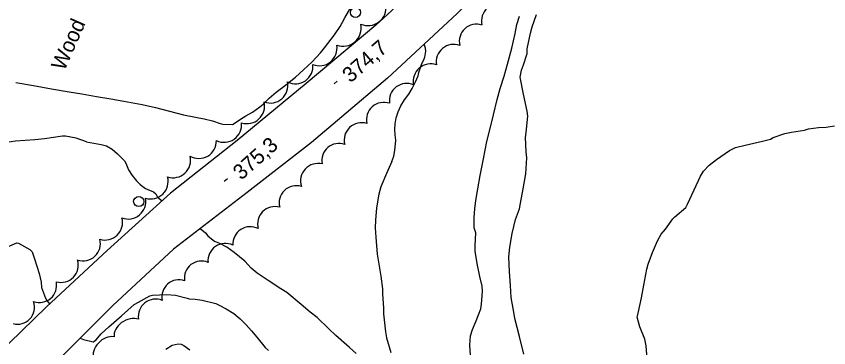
# Model space of a CAD drawing. Extents: x 287698 to 290158, y 5234163 to 5237182.
# Drawn here: x 287954.6 to 288115.1, y 5235215.8 to 5235281.3 of the extents above; entities that cross this region are included whole.
import ezdxf

# ---------------------------------------------------------------- set-up
doc = ezdxf.new("R2010")
doc.units = 0
for name, color, linetype in [('Niveau 1', 7, 'Continuous'), ('Niveau 2', 7, 'Continuous'), ('Niveau 21', 7, 'Continuous'), ('Niveau 3', 7, 'Continuous'), ('Niveau 36', 7, 'Continuous'), ('Niveau 44', 7, 'Continuous')]:
    doc.layers.add(name, color=color, linetype=linetype)

msp = doc.modelspace()

# ---------------------------------------------------------------- linework, layer by layer
at = {"layer": 'Niveau 1'}
for points in [[(288052.13, 5235235.69), (288052.56, 5235238.39), (288053.22, 5235241.12), (288054.04, 5235243.22), (288054.23, 5235244.36), (288054.74, 5235247.2), (288055.24, 5235250.18), (288055.44, 5235253.33), (288055.34, 5235254.52), (288055.19, 5235257.35), (288055.31, 5235258.29), (288055.68, 5235261.56), (288055.55, 5235262.52), (288054.8, 5235265.86), (288054.16, 5235269.25), (288054.42, 5235270.61), (288054.84, 5235271.68), (288055.51, 5235273.94), (288055.56, 5235274.82), (288056.17, 5235277.93), (288056.52, 5235279.18), (288057.36, 5235281.59)], [(288054.86, 5235214.53), (288054.01, 5235218.04), (288053.11, 5235221.56), (288052.87, 5235222.84), (288052.4, 5235225.76), (288052.22, 5235228.12), (288052.01, 5235230.77), (288051.9, 5235233.79), (288052.13, 5235235.69)], [(287984.12, 5235215.51), (287985.37, 5235216.29), (287986.56, 5235216.61), (287987.14, 5235216.52), (287987.72, 5235216.26), (287988.85, 5235215.42)]]:
    msp.add_lwpolyline(points, dxfattribs=at)
at = {"layer": 'Niveau 2'}
for points in [[(287954.49, 5235268.19), (287958, 5235267.57), (287961.58, 5235266.94), (287965.03, 5235266.36), (287967.53, 5235265.96), (287970.44, 5235265.45), (287973.26, 5235264.95), (287975.83, 5235264.5), (287979.49, 5235263.85), (287982.09, 5235263.26), (287984.87, 5235262.52), (287987.65, 5235261.83), (287990, 5235261.34), (287991.7, 5235261.04), (287993.38, 5235260.59), (287994.87, 5235260.07), (287995.38, 5235259.98), (287997.33, 5235259.9), (287997.81, 5235260.2), (287998.9, 5235260.97), (287999.92, 5235261.59), (288001.26, 5235262.34), (288002.69, 5235263.35), (288003.36, 5235263.94), (288004.59, 5235265.09), (288005.93, 5235266.27), (288007.49, 5235267.45), (288009.76, 5235269.23), (288011.34, 5235270.66), (288013.08, 5235272.29), (288014.68, 5235274.07), (288015.46, 5235275.04), (288017.48, 5235277.61), (288018.58, 5235279.27), (288019.54, 5235280.97), (288021.17, 5235283.78)], [(288045.36, 5235238.5), (288045.08, 5235239.51), (288045.04, 5235240.15), (288045.07, 5235241.5), (288045.17, 5235243.22), (288045.4, 5235244.9), (288045.8, 5235247.19), (288046.27, 5235249.82), (288046.9, 5235253.11), (288047.58, 5235256.55), (288048.14, 5235258.82), (288048.89, 5235261.77), (288049.61, 5235264.8), (288050.21, 5235267), (288050.97, 5235269.41), (288051.62, 5235271.8), (288052.48, 5235274.98), (288053.19, 5235277.84), (288053.52, 5235279.64), (288053.99, 5235281.29)], [(288034.13, 5235270.19), (288034.71, 5235271.91), (288035.07, 5235272.5), (288035.32, 5235273.18), (288035.52, 5235274.4), (288035.46, 5235274.94), (288035.21, 5235275.77)], [(288028.8, 5235252.59), (288029.21, 5235253.64), (288029.4, 5235254.75), (288029.59, 5235256.81), (288029.43, 5235257.84), (288029.36, 5235258.9), (288029.46, 5235260.04), (288029.67, 5235261.2), (288030.03, 5235262.37), (288030.54, 5235263.56), (288031.32, 5235264.76), (288032.14, 5235265.89), (288032.84, 5235267.03), (288033.48, 5235268.31), (288034, 5235269.51), (288034.13, 5235270.19)], [(288079.34, 5235212.75), (288079.07, 5235216.19), (288078.75, 5235217.5), (288077.82, 5235219.95), (288077.28, 5235221.88), (288077.44, 5235222.62), (288078.15, 5235225.65), (288078.61, 5235228.16), (288079.19, 5235231.33), (288079.45, 5235232.32), (288080.31, 5235234.63), (288081.28, 5235236.94), (288082.04, 5235238.23), (288082.87, 5235239.25), (288084.32, 5235241.29), (288084.71, 5235241.65), (288086.89, 5235243.51), (288087.22, 5235244.14), (288088.5, 5235246.97), (288089.8, 5235249.72), (288090.39, 5235250.69), (288091.47, 5235251.85), (288092.93, 5235252.98), (288095.52, 5235254.79), (288096.71, 5235255.32), (288098.63, 5235255.82), (288102, 5235256.58), (288103.61, 5235257.03), (288104.14, 5235257.34), (288106.47, 5235258.14), (288107.74, 5235258.38), (288110.32, 5235258.79), (288111.11, 5235259.06), (288113.07, 5235259.29), (288114.63, 5235259.35), (288116.26, 5235259.64)], [(287968.46, 5235256.45), (287966.41, 5235257.17), (287964.32, 5235257.61), (287963.71, 5235257.59), (287960.15, 5235257.04), (287958.24, 5235256.89), (287954.47, 5235256.57), (287952.74, 5235256.31), (287950.27, 5235255.79), (287948.63, 5235255.22), (287945.89, 5235254.32), (287943.82, 5235253.76), (287941.14, 5235253.22), (287938.63, 5235252.6), (287936.4, 5235251.93), (287932.8, 5235250.77), (287928.51, 5235249.72)], [(287968.46, 5235256.45), (287971.35, 5235255.94), (287972.43, 5235255.66), (287973.53, 5235255.03), (287974.61, 5235254.11), (287976, 5235252.71), (287976.21, 5235252.25), (287976.75, 5235250.93), (287977.48, 5235249.84), (287978.33, 5235248.79), (287979.06, 5235248.04), (287980.11, 5235247.27), (287980.59, 5235247.07), (287981.7, 5235246.59), (287982.14, 5235246.17), (287982.49, 5235245.56), (287983.4, 5235244.79)], [(288028.8, 5235252.59), (288027.75, 5235250.23), (288026.62, 5235247.56), (288026.25, 5235246.11), (288025.78, 5235243.43), (288025.54, 5235240.98), (288025.51, 5235239.47), (288025.64, 5235237.67), (288025.91, 5235234.27), (288026.15, 5235232.71), (288026.61, 5235229.97), (288026.92, 5235227.43), (288026.93, 5235226.48), (288027.14, 5235223.63), (288027.13, 5235222.53), (288027.51, 5235218.95), (288027.73, 5235217.77), (288028.6, 5235214.84)], [(287990.93, 5235239.34), (287992.01, 5235238.48), (287992.41, 5235237.9), (287993.82, 5235236.8)], [(288051.57, 5235194.51), (288048.21, 5235199.51), (288046.19, 5235206.08), (288045.57, 5235207.65), (288045.16, 5235209.12), (288044.59, 5235212.31), (288044.31, 5235214.37), (288044.21, 5235216.31), (288044.34, 5235218.15), (288044.73, 5235219.38), (288045.48, 5235221.13), (288046.35, 5235223.48), (288046.52, 5235224.39), (288046.73, 5235226.99), (288046.64, 5235227.95), (288046.16, 5235229.89), (288045.75, 5235232.1), (288045.27, 5235234.83), (288045.27, 5235236.01), (288045.36, 5235238.5)], [(287930.34, 5235218.96), (287932.74, 5235221.21), (287935.21, 5235222.57), (287938.01, 5235224.07), (287938.61, 5235224.51), (287940.47, 5235226.24), (287942.74, 5235228.41), (287945.24, 5235230.68), (287947.23, 5235232.35), (287947.85, 5235232.68), (287950.41, 5235234.19), (287951.23, 5235234.79), (287953.29, 5235235.95), (287954.67, 5235236.51), (287955.04, 5235236.48), (287957.3, 5235235.19), (287957.76, 5235234.73), (287958.21, 5235233.37), (287959.13, 5235230.47), (287959.52, 5235228.74), (287959.59, 5235227.73), (287960.34, 5235225.61), (287960.63, 5235225.16), (287961.15, 5235224.46)], [(288021.76, 5235214.68), (288020.43, 5235215.89), (288017.76, 5235218.22), (288016.33, 5235219.57), (288014.07, 5235221.75), (288012.64, 5235222.81), (288010.86, 5235224.32), (288008.04, 5235226.72), (288006.88, 5235227.47), (288004.34, 5235229.12), (288002.19, 5235230.52), (288000.99, 5235231.54), (287999.75, 5235232.91), (287997.63, 5235234.65), (287996.22, 5235235.64), (287994.84, 5235236.37), (287993.82, 5235236.8)], [(287967.24, 5235217.71), (287967.86, 5235217.43), (287969.75, 5235216.96), (287970.28, 5235217.3), (287971.39, 5235218.56), (287972.9, 5235219.96), (287975.35, 5235222.13), (287977.88, 5235224.32), (287978.77, 5235224.84), (287980.97, 5235226.03), (287981.53, 5235226.21), (287984.3, 5235226.33), (287986.05, 5235226.2), (287988.33, 5235225.63), (287988.74, 5235225.48)], [(287988.74, 5235225.48), (287989.93, 5235225.42), (287991.29, 5235225.18), (287994, 5235224.57), (287994.7, 5235224.24), (287996.09, 5235223.49), (287997.56, 5235222.56), (287998.84, 5235221.52), (287999.98, 5235220.36), (288001.09, 5235219.13), (288002.11, 5235217.88), (288003.76, 5235215.89), (288004.41, 5235215.25)]]:
    msp.add_lwpolyline(points, dxfattribs=at)
at = {"layer": 'Niveau 21'}
for points in [[(288145.74, 5235463.07), (288133.14, 5235440.74), (288124.26, 5235424.52), (288112.67, 5235403.12), (288103.48, 5235387.01), (288090.93, 5235364.82), (288077.15, 5235342.5), (288067.25, 5235327.63), (288058.83, 5235315.4), (288048.75, 5235302.52), (288038.43, 5235291.29), (288025.6, 5235279.48), (288011.9, 5235268.02), (287998.22, 5235256.72), (287985.09, 5235246.31), (287972.54, 5235235), (287960.54, 5235223.89), (287948.27, 5235211.98)], [(288155.23, 5235459.52), (288143.04, 5235438.77), (288132.78, 5235420.12), (288119.66, 5235397.91), (288107.85, 5235376.49), (288093.91, 5235353.38), (288082.05, 5235333.18), (288072.8, 5235318.93), (288064.64, 5235307.5), (288054.21, 5235294.6), (288041.68, 5235281.78), (288027.97, 5235269.04), (288012.89, 5235256.33), (288000.22, 5235246.49), (287985.65, 5235235.27), (287973.66, 5235224.14), (287962.81, 5235213.28)]]:
    msp.add_lwpolyline(points, dxfattribs=at)
at = {"layer": 'Niveau 3'}
for p, q in [((288017.39, 5235267.93), (288018.02, 5235268.43)), ((287995.67, 5235248.73), (287996.3, 5235249.22))]:
    msp.add_line(p, q, dxfattribs=at)
at = {"layer": 'Niveau 36'}
for centre in [(288021.62, 5235282.02), (287978.78, 5235244.67)]:
    msp.add_ellipse(centre, major_axis=(0.918, 0.397), ratio=0.999992, dxfattribs=at)
at = {"layer": 'Niveau 44'}
for centre, major_axis, ratio, start_param, end_param in [((288024.06, 5235283.03), (2.15, -2.91), 0.994327, 5.241811, 7.354856), ((288049.94, 5235280.31), (-2.27, 2.6), 0.99517, 5.242942, 7.360364), ((288019.13, 5235278.94), (2.38, -2.71), 0.999995, 5.220804, 7.349479), ((288045.54, 5235276.29), (-2.28, 2.56), 0.995131, 5.241974, 7.362236), ((288014.5, 5235274.96), (2.16, -2.71), 0.999864, 5.217353, 7.348235), ((288041.01, 5235272.28), (-2.23, 2.63), 0.99565, 5.219492, 7.334743), ((288009.76, 5235271.35), (2.82, 1.97), 0.995603, 3.633628, 5.79115), ((288036.47, 5235268.42), (-2.13, 2.71), 0.998486, 5.273311, 7.391496), ((288004.81, 5235267.57), (2.61, 2.25), 0.995622, 3.63293, 5.791848), ((288031.74, 5235264.57), (-2.1, 2.73), 0.997563, 5.219227, 7.343987), ((288000.18, 5235263.54), (2.36, -2.56), 0.999995, 5.223305, 7.349391), ((288027.21, 5235260.83), (-2.3, 2.56), 0.998398, 5.216258, 7.342662), ((287995.64, 5235259.85), (2.01, -2.84), 0.999978, 5.217556, 7.348485), ((288022.82, 5235256.8), (-2.37, 2.5), 0.99933, 5.217739, 7.341853), ((287990.67, 5235256.64), (1.28, -3.21), 0.999831, 5.369869, 7.496981), ((288018.42, 5235252.7), (-2.32, 2.61), 0.977194, 5.228285, 7.311493), ((287985.55, 5235252.86), (2.31, -2.61), 0.995578, 5.248538, 7.366129), ((288014.22, 5235248.74), (-2.34, 2.55), 0.999393, 5.299223, 7.424001), ((287981.13, 5235248.67), (2.27, -2.63), 0.998694, 5.27202, 7.401078), ((288009.96, 5235244.38), (-2.42, 2.46), 0.990651, 5.213709, 7.32629), ((287976.7, 5235244.69), (2.24, -2.65), 0.999342, 5.218187, 7.34226), ((288005.69, 5235240.26), (-2.37, 2.49), 0.995788, 5.243501, 7.36985), ((287972.11, 5235240.56), (2.42, -2.5), 0.998434, 5.221892, 7.343593), ((288000.84, 5235236.26), (-1.88, 2.91), 0.991788, 5.235522, 7.34457), ((287967.74, 5235236.44), (2.41, -2.52), 0.991713, 5.212351, 7.325341), ((287995.89, 5235232.99), (-0.94, 3.29), 0.999961, 5.545676, 7.672493), ((287963.37, 5235232.18), (2.54, -2.4), 0.989918, 5.214621, 7.324278), ((287991.25, 5235229.47), (-2.13, 2.76), 0.977452, 5.244074, 7.330201), ((287986.8, 5235225.79), (-2.28, 2.62), 0.979478, 5.247941, 7.334801), ((287959.1, 5235228.23), (2.3, -2.66), 0.977185, 5.239879, 7.324387), ((287954.82, 5235223.9), (1.09, -3.27), 0.974982, 5.695429, 7.851631), ((287982.13, 5235221.99), (-2.03, 2.77), 0.997883, 5.258706, 7.381627), ((287977.14, 5235218.75), (-2.99, -1.64), 0.771703, 3.794962, 5.950694), ((287972.79, 5235214.92), (-2.31, -2.51), 0.785131, 3.636506, 5.788272)]:
    msp.add_ellipse(centre, major_axis=major_axis, ratio=ratio, start_param=start_param, end_param=end_param, dxfattribs=at)

# ---------------------------------------------------------------- texts
at = {"layer": 'Niveau 3'}
for s, rotation, p in [('374,7', 40.8502, (288020.61, 5235268)), ('375,3', 41.5391, (287999.04, 5235248.78))]:
    msp.add_text(s, height=3, rotation=rotation, dxfattribs=at).set_placement(p)
at = {"layer": 'Niveau 44'}
msp.add_text('Wood', height=3, rotation=66.1212, dxfattribs=at).set_placement((287964.1, 5235270.33))

doc.saveas('drawing.dxf')
